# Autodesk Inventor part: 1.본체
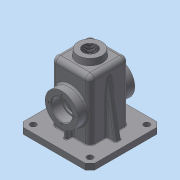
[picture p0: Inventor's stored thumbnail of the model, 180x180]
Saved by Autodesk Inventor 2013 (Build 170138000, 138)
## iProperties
Created: 2018-10
Part Number: 1.본체
Material: 일반
Document SubType Name: Modeling
Designer: Administrator
Density: 1 g/cm^3
Author: Administrator
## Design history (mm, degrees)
sketch "스케치1"
  geometry: L1 (-32.5, 32.5)-(32.5, 32.5); L2 (32.5, 32.5)-(32.5, -32.5); L3 (32.5, -32.5)-(-32.5, -32.5); L4 (-32.5, -32.5)-(-32.5, 32.5); L5 (-32.5, 32.5)-(32.5, -32.5); L6 (32.5, 32.5)-(-32.5, -32.5); 1 further point
  constraints: 12 end point, 2 midpoint, 2 parallel, 1 horizontal, 1 perpendicular
  dimensions: "d0" = 65 distance of L2.end L3.end; "d1" = 65 distance of L1.end L2.end
extrude "돌출1" new body sketch "스케치1" stored distance "d2" = 110; taper "d3" = 0 deg
fillet "모깎기1" dims "d4" = 8
fillet "모깎기2" dims "d5" = 8
feature "쉘1" dims "d6" = 5
sketch "스케치2"
  geometry: C1 r 27.5 at (24.5, 55); 1 further point
  constraints: 1 centre point, 1 coincident
  dimensions: "d7" = 55 diameter of C1
extrude "돌출2" join sketch "스케치2" distance "d8" = 15; taper "d9" = 0 deg
hole "구멍1" diameter "d12" = 30; stored, may be unused: countersink angle "d16" = 90 deg, drill point angle "d18" = 0 deg; dims "d10" = 10, "d11" = 10, "d13" = 6, "d14" = 35, "d15" = 17, "d17" = 8
sketch "스케치3"
  geometry: L1 (0, 0)-(0, 21); C1 r 27.5 at (0, 0) reference; 1 further point
  constraints: 2 end point, 1 coincident, 1 vertical
  dimensions: "d19" = 21 distance of L1.start L1.end
hole "구멍2" sketch "스케치3" at (0, 21) diameter "d20" = 3.242; stored, may be unused: countersink angle "d24" = 90 deg, drill point angle "d26" = 118 deg; dims "d21" = 8, "d22" = 35, "d23" = 17, "d25" = 10
node "작업 평면1"
sketch "스케치4"
  geometry: C1 r 20 at (0, 0); 1 further point
  constraints: 1 centre point, 1 coincident
  dimensions: "d31" = 40 diameter of C1
extrude "돌출3" join sketch "스케치4" stored distance "d32" = 15; taper "d33" = 7 deg
hole "구멍3" diameter "d36" = 22.835; stored, may be unused: countersink angle "d40" = 90 deg, drill point angle "d42" = 118 deg; dims "d34" = 10, "d35" = 10, "d37" = 30, "d38" = 35, "d39" = 17, "d41" = 10
sketch "스케치5"
  geometry: L1 (24.5, 32.5)-(-24.5, 32.5) reference; L2 (-32.5, 24.5)-(-32.5, -24.5) reference; L3 (-24.5, -32.5)-(24.5, -32.5) reference; L4 (32.5, -24.5)-(32.5, 24.5) reference; L5 (-60, 60)-(60, 60); L6 (60, 60)-(60, -60); L7 (60, -60)-(-60, -60); L8 (-60, -60)-(-60, 60); L9 (-60, 60)-(60, -60); L10 (60, 60)-(-60, -60); A1 r 8 centre (-24.5, 24.5) between (-24.5, 32.5) and (-32.5, 24.5) reference; A2 r 8 centre (-24.5, -24.5) between (-32.5, -24.5) and (-24.5, -32.5) reference; A3 r 8 centre (24.5, -24.5) between (24.5, -32.5) and (32.5, -24.5) reference; A4 r 8 centre (24.5, 24.5) between (32.5, 24.5) and (24.5, 32.5) reference; 1 further point
  constraints: 12 end point, 2 midpoint, 2 parallel, 1 horizontal, 1 perpendicular
  dimensions: "d43" = 120 distance of L6.end L7.end; "d44" = 120 distance of L5.end L6.end
extrude "돌출4" join sketch "스케치5" distance "d45" = 10; taper "d46" = 0 deg
chamfer "모따기1" distance "d47" = 8; stored, may be unused: second distance "d48" = 2, angle "d49" = 45 deg
sketch "스케치6"
  geometry: C1 r 5 at (-47.5, 47.5); C2 r 5 at (47.5, 47.5); C3 r 5 at (47.5, -47.5); C4 r 5 at (-47.5, -47.5); 1 further point
  constraints: 4 centre point
  dimensions: "d50" = 10 diameter of C1; "d51" = 10 diameter of C2; "d52" = 95 distance of C2.centre C1.centre; "d53" = 47.5 horizontal distance of C2.centre point (0, 0); "d54" = 47.5 horizontal distance of C2.centre point (0, 0); "d55" = 10 diameter of C3; "d56" = 10 diameter of C4; "d57" = 95 distance of C3.centre C4.centre; "d58" = 47.5 horizontal distance of C3.centre point (0, 0); "d59" = 95 distance of C3.centre C2.centre; "d60" = 95 distance of C1.centre C4.centre; "d61" = 47.5 horizontal distance of point (0, 0) C1.centre
extrude "돌출5" cut sketch "스케치6" stored distance "d62" = 10; taper "d63" = 0 deg
sketch "스케치7"
  geometry: L1 (-48, -45)-(-40.61, -3.09); L2 (20, 65)-(21.228, 55) reference; L3 (21.228, 55)-(24.5, 55) reference; L4 (32.5, 47)-(32.5, -45) reference; L5 (32.5, -45)-(60, -45) reference; L6 (60, -45)-(60, -55) reference; L7 (60, -55)-(27.5, -55) reference; L8 (27.5, -55)-(27.5, 47) reference; L9 (24.5, 50)-(11.418, 50) reference; L10 (11.418, 50)-(11.418, 65) reference; L11 (11.418, 65)-(20, 65) reference; L12 (-21.228, 55)-(-20, 65) reference; L13 (-20, 65)-(-11.418, 65) reference; L14 (-11.418, 65)-(-11.418, 50) reference; L15 (-11.418, 50)-(-24.5, 50) reference; L16 (-27.5, 47)-(-27.5, -55) reference; L17 (-27.5, -55)-(-60, -55) reference; L18 (-60, -55)-(-60, -45) reference; L19 (-60, -45)-(-32.5, -45) reference; L20 (-32.5, -45)-(-32.5, 47) reference; L21 (-24.5, 55)-(-21.228, 55) reference; A1 r 8 centre (24.5, 47) between (32.5, 47) and (24.5, 55) reference; A2 r 3 centre (24.5, 47) between (27.5, 47) and (24.5, 50) reference; A3 r 3 centre (-24.5, 47) between (-24.5, 50) and (-27.5, 47) reference; A4 r 8 centre (-24.5, 47) between (-24.5, 55) and (-32.5, 47) reference; 1 further point
  constraints: 2 end point, 1 point on line
  dimensions: "d64" = 12 distance from line of L1.start L18; "d65" = 10 deg angle of L1 L18
feature "리브1" sketch "스케치7" dims "d66" = 1, "d67" = 10, "d68" = 0, "d69" = 0, "d70" = 1, "d71" = 1
sketch "스케치8"
  geometry: L1 (-42.5, -45)-(-42.5, -27.5); L2 (36.526, -21)-(37.5, -22.621) reference; L3 (37.5, -22.621)-(47.5, -22.621) reference; L4 (47.5, -22.621)-(47.5, -27.5) reference; L5 (47.5, -27.5)-(32.5, -27.5) reference; L6 (32.5, -27.5)-(32.5, -45) reference; L7 (32.5, -45)-(60, -45) reference; L8 (60, -45)-(60, -55) reference; L9 (60, -55)-(27.5, -55) reference; L10 (27.5, -55)-(27.5, -15) reference; L11 (27.5, -15)-(30.5, -15) reference; L12 (30.5, -15)-(30.5, -17.5) reference; L13 (30.5, -17.5)-(47.5, -17.5) reference; L14 (47.5, -17.5)-(47.5, -19.379) reference; L15 (47.5, -19.379)-(37.5, -19.379) reference; L16 (37.5, -19.379)-(36.526, -21) reference; L17 (32.5, 27.5)-(47.5, 27.5) reference; L18 (47.5, 27.5)-(47.5, 22.621) reference; L19 (47.5, 22.621)-(37.5, 22.621) reference; L20 (37.5, 22.621)-(36.526, 21) reference; L21 (36.526, 21)-(37.5, 19.379) reference; L22 (37.5, 19.379)-(47.5, 19.379) reference; L23 (47.5, 19.379)-(47.5, 17.5) reference; L24 (47.5, 17.5)-(30.5, 17.5) reference; L25 (30.5, 17.5)-(30.5, 15) reference; L26 (30.5, 15)-(27.5, 15) reference; L27 (27.5, 15)-(27.5, 47) reference; L28 (24.5, 50)-(11.418, 50) reference; L29 (11.418, 50)-(11.418, 65) reference; L30 (11.418, 65)-(20, 65) reference; L31 (20, 65)-(21.228, 55) reference; L32 (21.228, 55)-(24.5, 55) reference; L33 (32.5, 47)-(32.5, 27.5) reference; L34 (-37.5, -22.621)-(-36.526, -21) reference; L35 (-36.526, -21)-(-37.5, -19.379) reference; L36 (-37.5, -19.379)-(-47.5, -19.379) reference; L37 (-47.5, -19.379)-(-47.5, -17.5) reference; L38 (-47.5, -17.5)-(-30.5, -17.5) reference; L39 (-30.5, -17.5)-(-30.5, -15) reference; L40 (-30.5, -15)-(-27.5, -15) reference; L41 (-27.5, -15)-(-27.5, -55) reference; L42 (-27.5, -55)-(-60, -55) reference; L43 (-60, -55)-(-60, -45) reference; L44 (-60, -45)-(-32.5, -45) reference; L45 (-32.5, -45)-(-32.5, -27.5) reference; L46 (-32.5, -27.5)-(-47.5, -27.5) reference; L47 (-47.5, -27.5)-(-47.5, -22.621) reference; L48 (-47.5, -22.621)-(-37.5, -22.621) reference; L49 (-47.5, 27.5)-(-32.5, 27.5) reference; L50 (-32.5, 27.5)-(-32.5, 47) reference; L51 (-24.5, 55)-(-21.228, 55) reference; L52 (-21.228, 55)-(-20, 65) reference; L53 (-20, 65)-(-11.418, 65) reference; L54 (-11.418, 65)-(-11.418, 50) reference; L55 (-11.418, 50)-(-24.5, 50) reference; L56 (-27.5, 47)-(-27.5, 15) reference; L57 (-27.5, 15)-(-30.5, 15) reference; L58 (-30.5, 15)-(-30.5, 17.5) reference; L59 (-30.5, 17.5)-(-47.5, 17.5) reference; L60 (-47.5, 17.5)-(-47.5, 19.379) reference; L61 (-47.5, 19.379)-(-37.5, 19.379) reference; L62 (-37.5, 19.379)-(-36.526, 21) reference; L63 (-36.526, 21)-(-37.5, 22.621) reference; L64 (-37.5, 22.621)-(-47.5, 22.621) reference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; A1 r 3 centre (24.5, 47) between (27.5, 47) and (24.5, 50) reference; A2 r 8 centre (24.5, 47) between (32.5, 47) and (24.5, 55) reference; A3 r 8 centre (-24.5, 47) between (-24.5, 55) and (-32.5, 47) reference; A4 r 3 centre (-24.5, 47) between (-24.5, 50) and (-27.5, 47) reference; 1 further point
  constraints: 2 end point, 2 point on line, 1 vertical
  dimensions: "d72" = 15 distance from line of L41.end L1
feature "리브2" sketch "스케치8" dims "d73" = 1, "d74" = 6, "d75" = 0, "d76" = 0, "d77" = 1, "d78" = 1
fillet "모깎기3" dims "d79" = 3
fillet "모깎기4" dims "d80" = 3
fillet "모깎기5" dims "d81" = 3
fillet "모깎기6" dims "d82" = 3
fillet "모깎기7" dims "d83" = 1
chamfer "모따기2" distance "d84" = 1; stored, may be unused: second distance "d85" = 2, angle "d86" = 45 deg
fillet "모깎기8" dims "d87" = 0.3
sketch "스케치10"
  geometry: L1 (57, 0)-(57, 91) reference; L2 (44.5, -18)-(4.5, -18) reference; 1 further point
  constraints: 1 other
  dimensions: "d88" = 32.5 distance from line of point (24.5, 8) L1; "d89" = 26 distance from line of point (24.5, 8) L2
feature "엠보싱1" sketch "스케치10" dims "d0" = 65, "d1" = 65, "d90" = 0.5, "d91" = 0
node "솔리드1"
pattern_circular "원형 패턴1" dims angle "d28" = 360 deg
mirror "대칭1"
mirror "대칭2"
mirror "대칭3"
node "절단 모서리 투영1"
node "절단 모서리 투영2"
other parameters: "d30" = 65
